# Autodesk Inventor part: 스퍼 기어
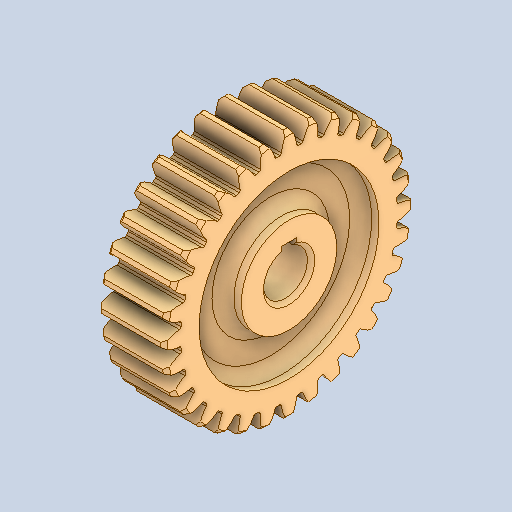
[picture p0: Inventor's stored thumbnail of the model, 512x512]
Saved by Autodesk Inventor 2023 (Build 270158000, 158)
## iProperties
Created: 2026-06
Part Number: 스퍼 기어
Material: 강철, 합금
Document SubType Name: Modeling
Designer: home
Density: 7.73 g/cm^3
Appearance: 기본값
Author: jhkim
Sending System: Autodesk Inventor 2027
Preprocessor: ST-DEVELOPER v20.1
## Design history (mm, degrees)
feature "솔리드1"
node "솔리드2"
